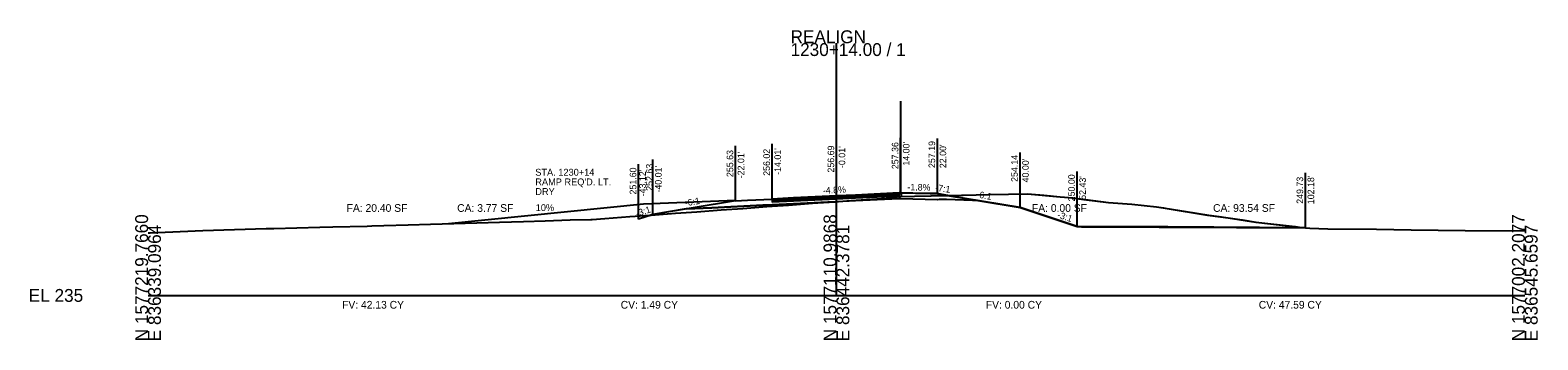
# Model space of a CAD drawing. Extents: x -26 to 6303, y -16 to 9563.
# Drawn here: x -25.7 to 302.8, y 8490.3 to 8557.8 of the extents above; entities that cross this region are included whole.
import ezdxf

# ---------------------------------------------------------------- set-up
doc = ezdxf.new("R2010")
doc.units = 0
for name, color, linetype in [('ASPHALT_19MM1', 7, 'Continuous'), ('ASPHALT_9_5MM1', 7, 'Continuous'), ('CONST_DCH', 7, 'Continuous'), ('CONST_LV3', 7, 'Continuous'), ('Draft_XS_Grid', 7, 'Continuous'), ('DTM_TEMP_DROP', 7, 'Continuous'), ('DTM_X_GROUND', 7, 'Continuous'), ('X_PROFILES_1', 7, 'Continuous'), ('X_TRANS_EOP', 7, 'Continuous'), ('XS_CELL', 7, 'Continuous'), ('XS_M_SHAPES_EARTHWORK', 7, 'Continuous'), ('XS_P_ASPHALT', 7, 'Continuous'), ('XS_P_DR_ASPHALT', 7, 'Continuous'), ('XS_P_DRIVEWAY', 7, 'Continuous'), ('XS_P_GROUND', 7, 'Continuous'), ('XS_P_SHOULDER', 7, 'Continuous'), ('XS_P_SUBGRADE_GRANULAR', 7, 'Continuous'), ('XS_P_SUBGRADE_LEVELING', 7, 'Continuous'), ('XS_P_SUBGRADE_MILLING', 7, 'Continuous'), ('XS_P_TX_CLEARZONE', 7, 'Continuous'), ('XS_P_TX_FS_BS', 7, 'Continuous'), ('XS_PLAN_CLEAR_ZONE', 7, 'Continuous'), ('XS_SHEET_EW_TX_AREA', 7, 'Continuous'), ('XS_SHEET_EW_TX_VOLUME', 7, 'Continuous')]:
    doc.layers.add(name, color=color, linetype=linetype)

msp = doc.modelspace()

# ---------------------------------------------------------------- linework, layer by layer
at = {"layer": 'ASPHALT_19MM1'}
msp.add_lwpolyline([(135.99, 8520.5), (135.99, 8520.41), (140.64, 8520.64), (149.99, 8521.09), (154.17, 8521.29), (163.66, 8521.74), (163.66, 8521.83), (163.66, 8522.01), (154.17, 8521.56), (149.99, 8521.36), (140.64, 8520.91), (135.99, 8520.68), (135.99, 8520.5)], dxfattribs=at)
at = {"layer": 'ASPHALT_9_5MM1'}
msp.add_lwpolyline([(135.99, 8520.93), (135.99, 8520.89), (140.64, 8521.12), (149.99, 8521.56), (154.17, 8521.77), (163.66, 8522.22), (163.66, 8522.26), (163.66, 8522.35), (154.17, 8521.89), (149.99, 8521.69), (140.64, 8521.24), (135.99, 8521.02), (135.99, 8520.93)], dxfattribs=at)
at = {"layer": 'CONST_LV3'}
for points in [[(164, 8522.33), (152.79, 8521.82), (150, 8521.69)], [(172, 8522.14), (170.4, 8522.18), (164, 8522.33)]]:
    msp.add_lwpolyline(points, dxfattribs=at)
at = {"layer": 'DTM_X_GROUND'}
msp.add_lwpolyline([(0, 8513.63), (0.46, 8513.65), (11.92, 8514.12), (25.75, 8514.56), (27.08, 8514.59), (27.4, 8514.6), (37.4, 8514.87), (40.24, 8514.94), (47.71, 8515.13), (48.75, 8515.16), (51.39, 8515.23), (56.67, 8515.37), (61.51, 8515.53), (66.63, 8515.66), (71.64, 8515.83), (76.58, 8515.96), (81.8, 8516.14), (86.52, 8516.26), (91.98, 8516.45), (96.46, 8516.57), (96.78, 8516.58), (99.5, 8516.78), (104.95, 8517.18), (109.53, 8517.51), (114.9, 8517.91), (119.55, 8518.24), (124.85, 8518.63), (129.57, 8518.97), (134.8, 8519.36), (139.59, 8519.71), (144.76, 8520.09), (149.6, 8520.44), (153.11, 8520.69), (158.78, 8521.06), (161.83, 8521.27), (163.01, 8521.45), (163.66, 8521.55), (166.98, 8521.63), (177.63, 8521.88), (183.27, 8521.99), (191.65, 8522.14), (198.78, 8521.51), (201.49, 8521.25), (201.72, 8521.18), (203.89, 8520.91), (209.31, 8520.26), (214.37, 8519.89), (219.77, 8519.3), (221.26, 8519.06), (221.63, 8519), (230.84, 8517.53), (231.44, 8517.42), (235.34, 8516.92), (241.41, 8516), (249.99, 8515), (251.2, 8514.83), (253.16, 8514.64), (257.1, 8514.5), (267.67, 8514.41), (275.2, 8514.29), (286.97, 8514.15), (300, 8514.07)], dxfattribs=at)
at = {"layer": 'X_TRANS_EOP'}
msp.add_line((164, 8522.33), (164, 8542.33), dxfattribs=at)
at = {"layer": 'XS_CELL'}
for p, q in [((150, 8500), (150, 8555)), ((0, 8500), (150, 8500)), ((150, 8500), (300, 8500))]:
    msp.add_line(p, q, dxfattribs=at)
at = {"layer": 'XS_M_SHAPES_EARTHWORK'}
for points in [[(164.14, 8521.56), (166.98, 8521.63), (174.28, 8521.8), (172.67, 8522.07), (171.99, 8522.19), (169.32, 8522.24), (163.99, 8522.36), (163.99, 8522.28), (163.99, 8522.24), (164.14, 8522.24), (164.14, 8521.56)], [(109.64, 8517.52), (114.9, 8517.91), (119.55, 8518.24), (124.85, 8518.63), (129.57, 8518.97), (134.8, 8519.36), (139.59, 8519.71), (144.76, 8520.09), (148.14, 8520.33), (140.64, 8519.97), (135.99, 8519.75), (134.65, 8519.68), (133.99, 8519.65), (122.83, 8519.12), (117.28, 8518.85), (109.99, 8517.63)], [(148.14, 8520.33), (149.6, 8520.44), (153.11, 8520.69), (158.78, 8521.06), (161.83, 8521.27), (163.01, 8521.45), (163.66, 8521.55), (164.14, 8521.56), (163.99, 8521.54), (163.66, 8521.53), (163.66, 8521.08), (154.17, 8520.62), (149.99, 8520.42)], [(106.88, 8516.6), (106.88, 8517.32), (109.53, 8517.51), (109.64, 8517.52)]]:
    msp.add_lwpolyline(points, close=True, dxfattribs=at)
at = {"layer": 'XS_P_ASPHALT'}
msp.add_lwpolyline([(164.14, 8522.37), (163.66, 8522.35), (163.66, 8522.26), (163.66, 8522.22), (163.51, 8522.21), (163.99, 8522.24), (163.99, 8522.28), (163.99, 8522.36), (164.14, 8522.37)], dxfattribs=at)
at = {"layer": 'XS_P_DRIVEWAY'}
for p, q in [((107.99, 8519.88), (65.44, 8515.62)), ((127.99, 8520.68), (107.99, 8519.88))]:
    msp.add_line(p, q, dxfattribs=at)
at = {"layer": 'XS_P_GROUND'}
for points in [[(174.29, 8521.8), (172.67, 8522.07), (171.99, 8522.19)], [(172, 8522.14), (190, 8519.14), (202.43, 8515)], [(127.99, 8520.63), (109.99, 8517.63), (106.88, 8516.6)], [(202.43, 8515), (203.43, 8514.98)], [(203.43, 8514.98), (237.2, 8514.84), (252.18, 8514.73)]]:
    msp.add_lwpolyline(points, dxfattribs=at)
at = {"layer": 'XS_P_SHOULDER'}
for points in [[(171.99, 8522.19), (169.32, 8522.24), (163.99, 8522.36)], [(127.99, 8520.63), (130.65, 8520.76), (135.99, 8521.02)]]:
    msp.add_lwpolyline(points, dxfattribs=at)
at = {"layer": 'XS_P_SUBGRADE_GRANULAR'}
for points in [[(117.28, 8518.85), (122.83, 8519.12), (133.99, 8519.65), (134.65, 8519.68), (135.99, 8519.75)], [(135.99, 8519.75), (140.64, 8519.97), (149.99, 8520.42)], [(163.66, 8521.08), (154.17, 8520.62), (149.99, 8520.42)], [(163.99, 8521.09), (163.66, 8521.08)], [(172, 8520.87), (163.99, 8521.09)], [(181.08, 8520.63), (179.66, 8520.69), (174, 8520.91), (172.4, 8520.88), (172, 8520.87)]]:
    msp.add_lwpolyline(points, dxfattribs=at)
at = {"layer": 'XS_P_SUBGRADE_LEVELING'}
msp.add_lwpolyline([(163.99, 8522.24), (164.14, 8522.24), (164.14, 8521.56), (163.99, 8521.54), (163.51, 8521.53), (163.51, 8522.21), (163.99, 8522.24)], dxfattribs=at)
at = {"layer": 'XS_P_SUBGRADE_MILLING'}
for points in [[(163.51, 8521.53), (163.51, 8521.53), (163.99, 8521.54), (164.14, 8521.56), (164.14, 8521.56)], [(163.51, 8521.53), (163.99, 8521.54), (164.14, 8521.56)]]:
    msp.add_lwpolyline(points, dxfattribs=at)
at = {"layer": 'XS_P_TX_CLEARZONE'}
for p, q in [((127.99, 8520.63), (127.99, 8532.63)), ((135.99, 8521.02), (135.99, 8533.02)), ((149.99, 8521.69), (149.99, 8533.69)), ((163.99, 8522.36), (163.99, 8534.36)), ((171.99, 8522.19), (171.99, 8534.19)), ((109.99, 8517.63), (109.99, 8529.63)), ((190, 8519.14), (190, 8531.14)), ((106.88, 8516.6), (106.88, 8528.6)), ((202.43, 8515), (202.43, 8527)), ((252.18, 8514.73), (252.18, 8526.73))]:
    msp.add_line(p, q, dxfattribs=at)
at = {"layer": 'XS_P_TX_FS_BS'}
msp.add_lwpolyline([(174.07, 8521.8), (180.45, 8521.94), (183.27, 8521.99), (187.46, 8522.06), (191.65, 8522.14), (195.21, 8521.83), (198.78, 8521.51), (201.49, 8521.25), (209.31, 8520.26), (214.37, 8519.89), (219.77, 8519.3), (221.63, 8519), (226.23, 8518.26), (231.14, 8517.47), (233.39, 8517.17), (235.34, 8516.92), (238.38, 8516.46), (241.41, 8516), (252.18, 8514.73), (222.22, 8514.95), (202.43, 8515), (190, 8519.14)], close=True, dxfattribs=at)
at = {"layer": 'XS_PLAN_CLEAR_ZONE'}
msp.add_lwpolyline([(135.99, 8520.75), (135.99, 8520.68), (140.64, 8520.91), (149.99, 8521.36), (154.17, 8521.56), (163.66, 8522.01), (163.66, 8522.08), (163.66, 8522.22), (154.17, 8521.77), (149.99, 8521.56), (140.64, 8521.12), (135.99, 8520.89), (135.99, 8520.75)], dxfattribs=at)

# ---------------------------------------------------------------- texts
at = {"layer": 'CONST_DCH'}
for p in [(163.58, 8522.23), (163.91, 8522.24), (135.91, 8520.9), (149.91, 8521.57)]:
    msp.add_text('X', height=0.24, dxfattribs=at).set_placement(p)
at = {"layer": 'Draft_XS_Grid'}
msp.add_text('-', height=0.0001, dxfattribs=at).set_placement((0, 8500))
at = {"layer": 'DTM_TEMP_DROP'}
for p in [(171.92, 8522.02), (174.21, 8521.68), (106.8, 8516.48)]:
    msp.add_text('X', height=0.24, dxfattribs=at).set_placement(p)
at = {"layer": 'X_PROFILES_1'}
for p in [(171.92, 8522.02), (189.92, 8519.02)]:
    msp.add_text('X', height=0.24, dxfattribs=at).set_placement(p)
at = {"layer": 'XS_CELL'}
for s, p in [('1230+14.00 / 1', (140, 8552.2)), ('REALIGN', (140, 8555)), ('EL 235', (-26, 8498.6))]:
    msp.add_text(s, height=2.8, dxfattribs=at).set_placement(p)
for s, p in [('N 1577219.7660', (0, 8490)), ('N 1577110.9868', (150, 8490)), ('N 1577002.2077', (300, 8490)), ('E 836339.0964', (2.8, 8490)), ('E 836442.3781', (152.8, 8490)), ('E 836545.6597', (302.8, 8490))]:
    msp.add_text(s, height=2.8, rotation=90, dxfattribs=at).set_placement(p)
at = {"layer": 'XS_P_ASPHALT'}
msp.add_text('X', height=0.24, dxfattribs=at).set_placement((202.35, 8514.88))
at = {"layer": 'XS_P_DR_ASPHALT'}
msp.add_text('X', height=0.24, dxfattribs=at).set_placement((109.91, 8517.51))
at = {"layer": 'XS_P_DRIVEWAY'}
for s, p in [('STA. 1230+14', (84.38, 8526.1)), ("RAMP REQ'D. LT.", (84.38, 8524)), ('DRY', (84.38, 8521.9)), ('10%', (84.47, 8518.39))]:
    msp.add_text(s, height=1.5, dxfattribs=at).set_placement(p)
at = {"layer": 'XS_P_SHOULDER'}
for p in [(171.91, 8522.07), (127.91, 8520.51)]:
    msp.add_text('X', height=0.24, dxfattribs=at).set_placement(p)
at = {"layer": 'XS_P_SUBGRADE_GRANULAR'}
for p in [(174.21, 8521.68), (106.8, 8516.48)]:
    msp.add_text('X', height=0.24, dxfattribs=at).set_placement(p)
at = {"layer": 'XS_P_TX_CLEARZONE'}
for s, p in [("-14.01'", (137.91, 8526.29)), ('256.69', (149.51, 8526.79)), ("-0.01'", (151.91, 8527.77)), ('257.36', (163.51, 8527.53)), ("14.00'", (165.92, 8528.3)), ('257.19', (171.51, 8527.78)), ("22.00'", (173.92, 8527.75)), ('255.63', (127.51, 8525.81)), ("-22.01'", (129.91, 8525.54)), ('256.02', (135.51, 8526.08)), ('254.14', (189.52, 8524.75)), ("40.00'", (191.92, 8524.64)), ('251.60', (106.4, 8522.01)), ("-43.12'", (108.47, 8521.61)), ('252.63', (109.96, 8522.81)), ("-40.01'", (111.91, 8522.43)), ('250.00', (201.95, 8520.51)), ("52.43'", (204.35, 8520.84)), ('249.73', (251.7, 8519.98)), ("102.18'", (254.1, 8519.89))]:
    msp.add_text(s, height=1.44, rotation=90, dxfattribs=at).set_placement(p)
at = {"layer": 'XS_P_TX_FS_BS'}
for s, rotation, p in [('-4.8%', 2.7481, (147.06, 8522.15)), ('-1.8%', 358.9483, (165.45, 8522.91)), ('-7:1', 351.5446, (171.44, 8522.83)), ('-6:1', 350.3912, (180.42, 8521.37)), ('-3:1', 18.4337, (106.52, 8517.11)), ('-6:1', 9.4642, (117.07, 8519.42)), ('-3:1', 341.565, (197.99, 8517))]:
    msp.add_text(s, height=1.44, rotation=rotation, dxfattribs=at).set_placement(p)
at = {"layer": 'XS_SHEET_EW_TX_AREA'}
for s, p in [('FA: 20.40 SF', (43.27, 8518.22)), ('CA: 3.77 SF', (67.36, 8518.22)), ('FA: 0.00 SF', (192.6, 8518.22)), ('CA: 93.54 SF', (232.07, 8518.22))]:
    msp.add_text(s, height=1.68, dxfattribs=at).set_placement(p)
at = {"layer": 'XS_SHEET_EW_TX_VOLUME'}
for s, p in [('FV: 42.13 CY', (42.28, 8497.12)), ('CV: 1.49 CY', (102.99, 8497.12)), ('FV: 0.00 CY', (182.55, 8497.12)), ('CV: 47.59 CY', (242.03, 8497.12))]:
    msp.add_text(s, height=1.68, dxfattribs=at).set_placement(p)

doc.saveas('drawing.dxf')
